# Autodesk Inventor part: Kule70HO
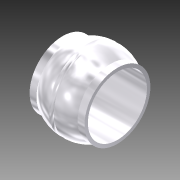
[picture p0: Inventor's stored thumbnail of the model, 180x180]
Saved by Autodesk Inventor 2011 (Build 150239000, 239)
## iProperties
Created: 2010-11
Document SubType Name: Modeling
Designer: tribel
Density: 1 g/cm^3
Author: tribel
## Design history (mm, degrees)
sketch "Sketch1"
  geometry: L1 (-45.5, 0)-(45.5, 0) reference; L2 (0, -11.589)-(0, 69.534) reference; L3 (-32.5, 39)-(-24.327, 39); L4 (-32.5, 39)-(-32.5, 0); L5 (-3, 0)-(-3, 45.867); L6 (-32.5, 35)-(-3, 35); L7 (32.5, 39)-(24.327, 39); L8 (32.5, 39)-(32.5, 0); L9 (32.5, 35)-(3, 35); L10 (3, 0)-(3, 45.867); L11 (-3, 35)-(3, 35); A1 r 12.445 centre (0, 57.945) between (-3, 45.867) and (3, 45.867); A2 r 45.965 centre (0, 0) between (24.327, 39) and (3, 45.867); A3 r 45.965 centre (0, 0) between (-3, 45.867) and (-24.327, 39)
  constraints: 18 end point, 7 symmetric about line, 6 point on circle, 6 point on line, 4 perpendicular, 3 centre point, 1 parallel
  dimensions: "d1" = 32.5 distance between parallel lines of L4 L2; "d2" = 3 distance between parallel lines of L5 L2; "d3" = 78 diameter of L3 L1; "d4" = 91 dimension on A1 L1; "d5" = 70 diameter of L9 L1; "d7" = 45.965 radius of A3
revolve "Revolution1" sketch "Sketch1" stored, may be unused: angle "d8" = 90 deg
body "Solid1"
other parameters: "d0" = 65.92, "d6" = 32.96
